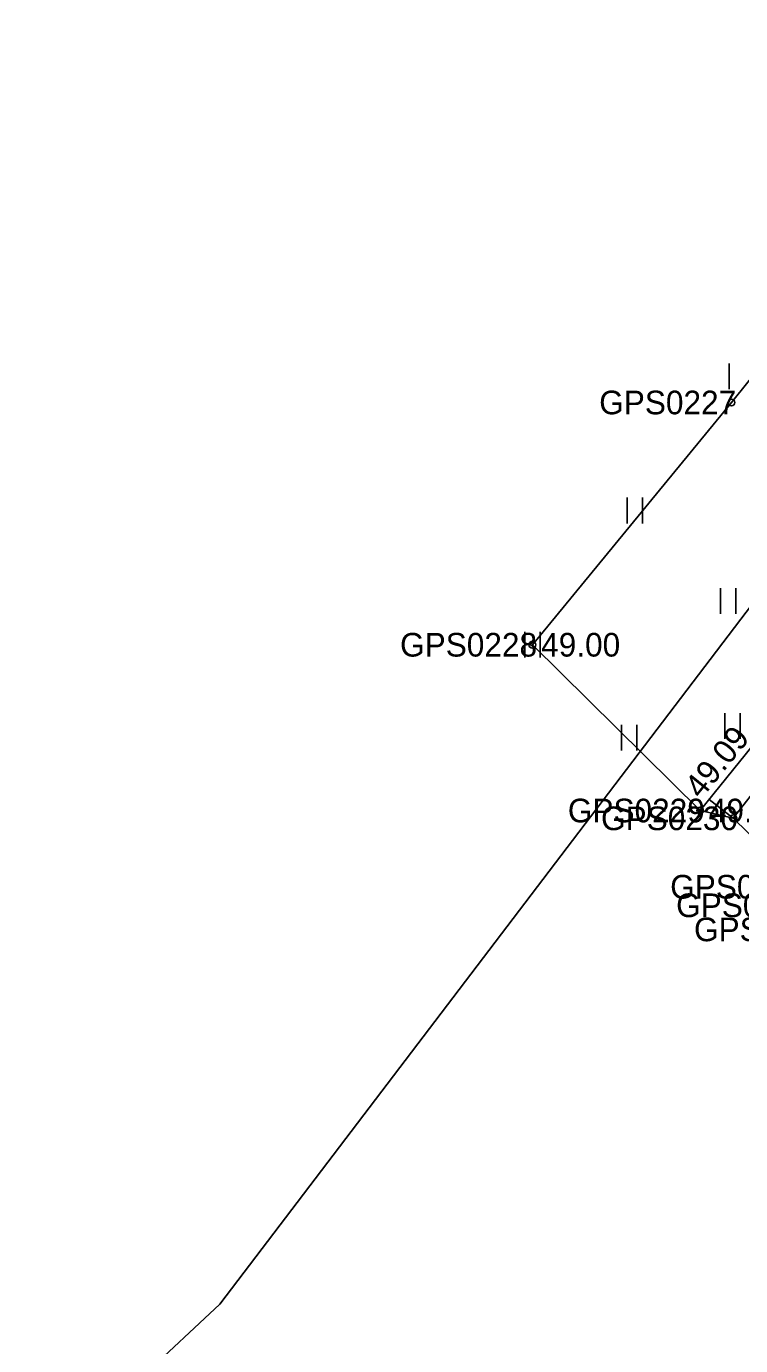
# Model space of a CAD drawing. Extents: x 563121 to 567545, y 6570841 to 6581299.
# Drawn here: x 565761.32 to 565782.48, y 6571805.07 to 6571844.15 of the extents above; entities that cross this region are included whole.
import ezdxf

# ---------------------------------------------------------------- set-up
doc = ezdxf.new("R2010")
doc.units = 0
for name, color, linetype in [('HALJASTUS', 7, 'Continuous'), ('KORGUS-EH2000', 7, 'Continuous'), ('MOOTKORG-EH2000', 7, 'Continuous'), ('MOOTMPUNKT', 7, 'Continuous'), ('MOOTNR', 7, 'Continuous'), ('MOOTPIIR', 7, 'Continuous'), ('PIIR', 7, 'Continuous'), ('RELJEEF', 7, 'Continuous')]:
    doc.layers.add(name, color=color, linetype=linetype)

msp = doc.modelspace()

# ---------------------------------------------------------------- linework, layer by layer
at = {"layer": 'HALJASTUS'}
for p, q in [((565782.142, 6571834.166), (565782.142, 6571833.405)), ((565779.112, 6571830.189), (565779.112, 6571829.428)), ((565779.567, 6571830.189), (565779.567, 6571829.428)), ((565781.879, 6571827.508), (565781.879, 6571826.747)), ((565782.334, 6571827.508), (565782.334, 6571826.747)), ((565776.081, 6571826.213), (565776.081, 6571825.451)), ((565776.536, 6571826.213), (565776.536, 6571825.451)), ((565782.012, 6571823.802), (565782.012, 6571823.041)), ((565782.467, 6571823.802), (565782.467, 6571823.041)), ((565778.95, 6571823.456), (565778.95, 6571822.695)), ((565779.405, 6571823.456), (565779.405, 6571822.695))]:
    msp.add_line(p, q, dxfattribs=at)
at = {"layer": 'KORGUS-EH2000'}
for centre in [(565782.207, 6571833.008), (565776.308, 6571825.832), (565781.278, 6571820.922), (565782.262, 6571820.691)]:
    msp.add_circle(centre, 0.1, dxfattribs=at)
at = {"layer": 'MOOTMPUNKT'}
for centre in [(565782.207, 6571833.008), (565776.308, 6571825.832), (565781.278, 6571820.922), (565782.262, 6571820.691)]:
    msp.add_circle(centre, 0.1, dxfattribs=at)
at = {"layer": 'MOOTPIIR'}
msp.add_lwpolyline([(565823.283, 6571871.288), (565820.939, 6571873.864), (565815.364, 6571875.639), (565813.463, 6571874.16), (565808.89, 6571868.083), (565802.021, 6571858.377), (565795.67, 6571849.773), (565782.207, 6571833.008), (565776.308, 6571825.832), (565781.278, 6571820.922), (565782.262, 6571820.691), (565783.542, 6571819.443), (565784.347, 6571818.115), (565785.017, 6571817.401), (565789.374, 6571812.429), (565790.175, 6571811.534), (565801.221, 6571799.668)], dxfattribs=at)
at = {"layer": 'PIIR'}
msp.add_lwpolyline([(564959.63, 6571567.88), (565247.22, 6571575.87), (565310, 6571592), (565385.09, 6571617.94), (565603.34, 6571696.36), (565663.71, 6571724.88), (565720.01, 6571762.52), (565767.05, 6571806.3), (565831.51, 6571891.07), (565894.85, 6571978.6), (565929.68, 6572026.82), (566028.25, 6572163.26), (566043.71, 6572184.75), (566068.58, 6572219.3), (566114.67, 6572283.35)], dxfattribs=at)
msp.add_lwpolyline([(565385.09, 6571617.94), (565348.3, 6571706.93), (565808.88, 6572174.3), (565817.95, 6572187.54), (565914.67, 6572223.63), (565927.34, 6572201.79), (566013.66, 6572213.36), (566028.25, 6572163.26), (565929.68, 6572026.82), (565869.35, 6572071.5), (565833.75, 6572019.48), (565773.79, 6571931.89), (565831.51, 6571891.07), (565767.05, 6571806.3), (565720.01, 6571762.52), (565663.71, 6571724.88), (565603.34, 6571696.36)], close=True, dxfattribs=at)
at = {"layer": 'RELJEEF'}
msp.add_line((565782.262, 6571820.691), (565781.546, 6571821.253), dxfattribs=at)
for points in [[(565781.278, 6571820.922), (565788.065, 6571829.31), (565794.289, 6571838.617), (565795.026, 6571841.487)], [(565782.262, 6571820.691), (565795.529, 6571837.598), (565795.847, 6571841.134), (565795.788, 6571841.243)]]:
    msp.add_lwpolyline(points, dxfattribs=at)

# ---------------------------------------------------------------- texts
at = {"layer": 'KORGUS-EH2000'}
msp.add_text(' 49.00', height=0.7, dxfattribs=at).set_placement((565776.308, 6571825.482))
msp.add_text(' 49.09', height=0.7, rotation=51.0237, dxfattribs=at).set_placement((565781.142, 6571821.032))
at = {"layer": 'MOOTKORG-EH2000'}
for s, p in [(' 49.00', (565776.308, 6571825.482)), (' 49.09', (565781.278, 6571820.572))]:
    msp.add_text(s, height=0.7, dxfattribs=at).set_placement(p)
at = {"layer": 'MOOTNR'}
for s, p in [('GPS0227 ', (565778.288, 6571832.658)), ('GPS0228 ', (565772.388, 6571825.482)), ('GPS0229 ', (565777.359, 6571820.572)), ('GPS0230 ', (565778.342, 6571820.341)), ('GPS0001 ', (565780.391, 6571818.314)), ('GPS0231 ', (565780.567, 6571817.765)), ('GPS0232 ', (565781.097, 6571817.051))]:
    msp.add_text(s, height=0.7, dxfattribs=at).set_placement(p)

doc.saveas('drawing.dxf')
